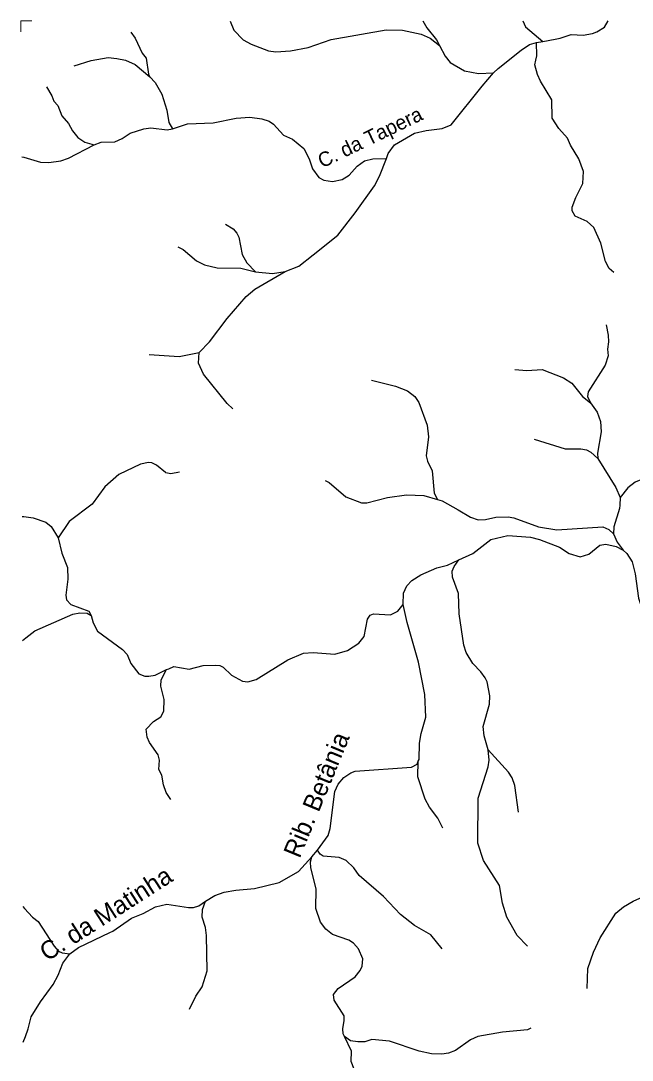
# Model space of a CAD drawing. Extents: x 473.9 to 500, y 7733.1 to 7760.8.
# Drawn here: x 473.88 to 477.26, y 7755.08 to 7760.81 of the extents above; entities that cross this region are included whole.
import ezdxf
from ezdxf.enums import TextEntityAlignment as Align

# ---------------------------------------------------------------- set-up
doc = ezdxf.new("R2010")
doc.units = 0
doc.header["$LTSCALE"] = 0.032
doc.layers.add('61', color=7, linetype='Continuous')
doc.layers.add('63', color=7, linetype='Continuous', lineweight=13)
doc.layers.add('7', color=7, linetype='Continuous', lineweight=25)

msp = doc.modelspace()

# ---------------------------------------------------------------- linework, layer by layer
at = {"layer": '63'}
msp.add_lwpolyline([(473.9466, 7760.8068), (473.885, 7760.8068), (473.885, 7760.7461)], dxfattribs=at)
at = {"layer": '7'}
for p, q in [((476.7287, 7760.6875), (476.7637, 7760.6941)), ((475.4907, 7756.1995), (475.5218, 7756.2363))]:
    msp.add_line(p, q, dxfattribs=at)
for points in [[(475.0392, 7760.8062), (475.0595, 7760.7562), (475.1122, 7760.7021), (475.1563, 7760.6781), (475.2516, 7760.6415), (475.2913, 7760.6366), (475.3731, 7760.6414), (475.4697, 7760.6609), (475.5973, 7760.7039), (475.8994, 7760.7575), (475.9898, 7760.7551), (476.0938, 7760.7344), (476.1422, 7760.7126), (476.1946, 7760.6706)], [(476.1017, 7760.807), (476.1246, 7760.7682), (476.1782, 7760.7022), (476.1946, 7760.6706)], [(476.6534, 7760.8074), (476.6684, 7760.7741), (476.6921, 7760.7542), (476.7637, 7760.6941)], [(476.7637, 7760.6941), (476.8311, 7760.7065), (476.8402, 7760.7081), (476.8603, 7760.7118), (476.9208, 7760.7318), (476.9864, 7760.728), (477.0377, 7760.7377), (477.0621, 7760.7461), (477.1033, 7760.772), (477.1242, 7760.8077)], [(474.4913, 7760.7452), (474.5162, 7760.7126), (474.555, 7760.6301), (474.5768, 7760.601), (474.5887, 7760.5127), (474.597, 7760.4988)], [(476.1946, 7760.6706), (476.2261, 7760.612), (476.2526, 7760.5783), (476.3318, 7760.5327), (476.4093, 7760.5179), (476.4912, 7760.5208)], [(476.4912, 7760.5208), (476.517, 7760.5446), (476.6444, 7760.6463), (476.6909, 7760.6771), (476.7287, 7760.6875)], [(477.156, 7759.4196), (477.1304, 7759.4426), (477.1088, 7759.4811), (477.0835, 7759.5818), (477.0456, 7759.6682), (477.0091, 7759.702), (476.9419, 7759.7306), (476.9264, 7759.76), (476.9265, 7759.7809), (476.9461, 7759.8341), (476.9837, 7759.9105), (476.9888, 7759.9765), (476.9626, 7760.0461), (476.9161, 7760.1215), (476.8995, 7760.1612), (476.8523, 7760.2142), (476.8158, 7760.2718), (476.8138, 7760.3726), (476.7509, 7760.4757), (476.7336, 7760.5118), (476.7197, 7760.5653), (476.7252, 7760.5901), (476.7307, 7760.6149), (476.7287, 7760.6875)], [(474.1795, 7760.5595), (474.2732, 7760.5886), (474.3676, 7760.6045), (474.4145, 7760.6005), (474.4629, 7760.5901), (474.5167, 7760.5668), (474.597, 7760.4988)], [(474.597, 7760.4988), (474.6262, 7760.4679), (474.6636, 7760.4035), (474.6909, 7760.3142), (474.7023, 7760.2465), (474.7217, 7760.2124)], [(475.9019, 7760.0492), (475.9107, 7760.0755), (475.9468, 7760.1235), (476.0566, 7760.1877), (476.121, 7760.2035), (476.2085, 7760.2137), (476.2591, 7760.2343), (476.4295, 7760.4481), (476.4912, 7760.5208)], [(474.026, 7760.4429), (474.0567, 7760.3935), (474.0669, 7760.3653), (474.0887, 7760.3405), (474.1118, 7760.2833), (474.1487, 7760.2423), (474.1707, 7760.2004), (474.2003, 7760.1646), (474.239, 7760.1393), (474.2891, 7760.1238)], [(474.7217, 7760.2124), (474.8036, 7760.2397), (474.9464, 7760.2459), (475.0719, 7760.2708), (475.1486, 7760.2774), (475.214, 7760.2677), (475.2554, 7760.254), (475.2782, 7760.2386), (475.3343, 7760.1778), (475.384, 7760.1545), (475.4452, 7760.1044), (475.475, 7760.0467), (475.4938, 7759.9913), (475.5282, 7759.9446), (475.556, 7759.9299), (475.6048, 7759.9213), (475.6572, 7759.9333), (475.6962, 7759.9572), (475.7403, 7760.0061), (475.7812, 7760.0366), (475.8267, 7760.0473), (475.9019, 7760.0492)], [(474.2891, 7760.1238), (474.3285, 7760.1386), (474.4043, 7760.1415), (474.4432, 7760.1586), (474.4884, 7760.1888), (474.5627, 7760.2131), (474.6024, 7760.2179), (474.6931, 7760.2076), (474.7217, 7760.2124)], [(473.8901, 7760.0586), (473.9012, 7760.0554), (473.9938, 7760.0287), (474.0393, 7760.0265), (474.105, 7760.0358), (474.1476, 7760.0498), (474.2891, 7760.1238)], [(475.3438, 7759.4258), (475.4181, 7759.4555), (475.4971, 7759.518), (475.6336, 7759.626), (475.7295, 7759.7484), (475.8347, 7759.8982), (475.8635, 7759.9509), (475.9019, 7760.0492)], [(475.0145, 7759.6859), (475.0569, 7759.6612), (475.0771, 7759.6365), (475.0867, 7759.6149), (475.1058, 7759.5199), (475.1323, 7759.4745), (475.1794, 7759.4242)], [(474.7503, 7759.5614), (474.7807, 7759.547), (474.8543, 7759.4856), (474.8976, 7759.4629), (474.9674, 7759.4467), (475.098, 7759.4451), (475.1794, 7759.4242)], [(474.8679, 7758.9796), (474.9264, 7759.0383), (475.0227, 7759.1674), (475.1274, 7759.289), (475.1758, 7759.3279), (475.3438, 7759.4258)], [(475.1794, 7759.4242), (475.2722, 7759.4155), (475.3438, 7759.4258)], [(477.1127, 7759.1312), (477.1245, 7759.0756), (477.1268, 7759.0384), (477.1196, 7758.997), (477.1235, 7758.9607), (477.1079, 7758.9101), (477.013, 7758.7623), (477.0098, 7758.7367), (477.0274, 7758.7028)], [(474.5921, 7758.9688), (474.7593, 7758.9584), (474.8679, 7758.9796)], [(475.0546, 7758.6684), (475.0225, 7758.6978), (474.892, 7758.8593), (474.8659, 7758.92), (474.8679, 7758.9796)], [(476.6101, 7758.8865), (476.6748, 7758.8806), (476.7606, 7758.8855), (476.8776, 7758.8408), (476.9233, 7758.81), (476.9825, 7758.7362), (477.0274, 7758.7028)], [(475.8194, 7758.8279), (475.9508, 7758.7942), (476.0169, 7758.7681), (476.0589, 7758.7369), (476.0792, 7758.704), (476.1261, 7758.5788), (476.1326, 7758.514), (476.1214, 7758.4105), (476.1274, 7758.3803), (476.1528, 7758.3268), (476.1643, 7758.2039), (476.1823, 7758.1699)], [(477.0274, 7758.7028), (477.0641, 7758.6508), (477.0811, 7758.6), (477.0851, 7758.5432), (477.0659, 7758.4243), (477.0675, 7758.3957)], [(476.7153, 7758.5026), (476.8872, 7758.4477), (476.9734, 7758.4492), (477.0049, 7758.4428), (477.0287, 7758.431), (477.0675, 7758.3957)], [(474.7611, 7758.3202), (474.7121, 7758.3114), (474.6844, 7758.317), (474.6828, 7758.3173), (474.6333, 7758.3578), (474.6069, 7758.3719), (474.5885, 7758.3739), (474.5448, 7758.3633), (474.4262, 7758.3072), (474.3485, 7758.2396), (474.2792, 7758.1433), (474.1512, 7758.0489), (474.092, 7757.9588)], [(477.0675, 7758.3957), (477.167, 7758.2356), (477.1911, 7758.1801)], [(475.5641, 7758.2746), (475.5857, 7758.2634), (475.6782, 7758.1837), (475.7631, 7758.1502), (475.7931, 7758.1508), (475.9072, 7758.1808), (476.0112, 7758.1943), (476.1078, 7758.1911), (476.1823, 7758.1699)], [(477.7102, 7758.2126), (477.6638, 7758.2344), (477.5594, 7758.2673), (477.4317, 7758.2905), (477.383, 7758.2905), (477.2949, 7758.2743), (477.2728, 7758.264), (477.2325, 7758.2342), (477.1911, 7758.1801)], [(476.1823, 7758.1699), (476.2095, 7758.1621), (476.2965, 7758.1119), (476.3653, 7758.0723), (476.4081, 7758.0572), (476.4474, 7758.0585), (476.5053, 7758.0717), (476.5723, 7758.074), (476.6031, 7758.069), (476.74, 7758.0188), (476.8402, 7758.0027), (477.0947, 7758.0195), (477.1284, 7758.0042), (477.1538, 7757.9796)], [(477.1911, 7758.1801), (477.1877, 7758.1383), (477.1862, 7758.1193), (477.1557, 7758.0183), (477.1538, 7757.9796)], [(473.8932, 7758.0761), (473.9025, 7758.075), (473.9538, 7758.0692), (474.0223, 7758.0443), (474.0529, 7758.0201), (474.092, 7757.9588)], [(474.092, 7757.9588), (474.112, 7757.8738), (474.1425, 7757.795), (474.1441, 7757.7308), (474.133, 7757.6415), (474.1377, 7757.6165), (474.1617, 7757.5903), (474.261, 7757.5538), (474.2734, 7757.5308)], [(476.3014, 7757.8363), (476.377, 7757.8713), (476.4772, 7757.9484), (476.5716, 7757.9706), (476.6967, 7757.9626), (476.7458, 7757.9495), (476.8553, 7757.9058), (476.9082, 7757.8722), (476.969, 7757.8536), (477.0183, 7757.8678), (477.079, 7757.9185), (477.111, 7757.9224), (477.1686, 7757.9096), (477.2076, 7757.8896)], [(477.1538, 7757.9796), (477.1743, 7757.934), (477.2076, 7757.8896)], [(477.2076, 7757.8896), (477.2271, 7757.8711), (477.2567, 7757.8251), (477.2734, 7757.7588), (477.292, 7757.6263), (477.3268, 7757.5202), (477.3543, 7757.481), (477.4148, 7757.4218), (477.4448, 7757.4073), (477.4983, 7757.3954), (477.816, 7757.3677), (477.9231, 7757.3226)], [(475.9943, 7757.5902), (475.9955, 7757.6523), (476.0134, 7757.6944), (476.0423, 7757.7237), (476.0912, 7757.7543), (476.1795, 7757.7922), (476.2384, 7757.8071), (476.3014, 7757.8363)], [(476.4633, 7756.7906), (476.4397, 7756.8662), (476.4357, 7756.9185), (476.4694, 7757.0417), (476.4725, 7757.0866), (476.4565, 7757.1648), (476.4464, 7757.1866), (476.4226, 7757.2204), (476.3771, 7757.2646), (476.3409, 7757.327), (476.3291, 7757.3665), (476.3026, 7757.5394), (476.2994, 7757.652), (476.266, 7757.741), (476.2641, 7757.7737), (476.2751, 7757.801), (476.3014, 7757.8363)], [(474.6888, 7757.232), (474.7012, 7757.237), (474.7291, 7757.2481), (474.8127, 7757.2337), (474.8914, 7757.2538), (474.9594, 7757.257), (474.9834, 7757.2539), (475.0014, 7757.2445), (475.0479, 7757.2019), (475.1073, 7757.1675), (475.1371, 7757.1649), (475.1823, 7757.1771), (475.357, 7757.2854), (475.4446, 7757.3219), (475.4982, 7757.3268), (475.617, 7757.3168), (475.6176, 7757.3167), (475.6858, 7757.3374), (475.7496, 7757.3775), (475.7792, 7757.414), (475.7968, 7757.5104), (475.8118, 7757.5319), (475.8301, 7757.5385), (475.9238, 7757.5344), (475.9648, 7757.5537), (475.9943, 7757.5902)], [(476.077, 7756.7266), (476.0817, 7756.737), (476.0829, 7756.826), (476.0923, 7756.8803), (476.1189, 7756.9704), (476.1133, 7757.0949), (476.0781, 7757.2735), (476.0155, 7757.4919), (475.9943, 7757.5902)], [(473.8942, 7757.3926), (473.9126, 7757.4071), (473.9616, 7757.4456), (474.1724, 7757.5366), (474.2112, 7757.5456), (474.2503, 7757.5423), (474.2734, 7757.5308)], [(474.2734, 7757.5308), (474.2839, 7757.4894), (474.3077, 7757.4446), (474.3362, 7757.4237), (474.4459, 7757.3434), (474.4713, 7757.3149), (474.4927, 7757.2664), (474.5357, 7757.2088), (474.5688, 7757.1953), (474.5915, 7757.1952), (474.6263, 7757.2012), (474.6888, 7757.232)], [(474.7122, 7756.5153), (474.6866, 7756.5546), (474.6726, 7756.5962), (474.6637, 7756.6509), (474.647, 7756.6814), (474.6502, 7756.7323), (474.6435, 7756.7614), (474.5949, 7756.8309), (474.5823, 7756.8591), (474.5773, 7756.9027), (474.6178, 7756.9462), (474.657, 7756.972), (474.6742, 7757.0021), (474.6765, 7757.0673), (474.6574, 7757.1403), (474.659, 7757.176), (474.6888, 7757.232)], [(476.6796, 7755.7078), (476.6215, 7755.7664), (476.565, 7755.867), (476.5416, 7755.9442), (476.5244, 7756.0414), (476.4363, 7756.1803), (476.4053, 7756.2761), (476.4068, 7756.523), (476.463, 7756.6952), (476.4677, 7756.7331), (476.4633, 7756.7906)], [(476.6303, 7756.4464), (476.6096, 7756.5923), (476.5951, 7756.6359), (476.5745, 7756.6675), (476.4633, 7756.7906)], [(475.5218, 7756.2363), (475.5801, 7756.3182), (475.5904, 7756.3559), (475.6167, 7756.5606), (475.6356, 7756.6006), (475.6657, 7756.637), (475.7042, 7756.6627), (475.7297, 7756.6718), (476.0392, 7756.6941), (476.07, 7756.7111), (476.077, 7756.7266)], [(476.2122, 7756.3578), (476.1846, 7756.413), (476.1386, 7756.4732), (476.1145, 7756.518), (476.0749, 7756.6416), (476.077, 7756.7266)], [(474.9037, 7755.9565), (474.9552, 7755.9868), (475.0069, 7756.0054), (475.0703, 7756.0166), (475.1743, 7756.0247), (475.3106, 7756.0583), (475.4172, 7756.1198), (475.4907, 7756.1995)], [(475.6703, 7755.2102), (475.6625, 7755.2249), (475.6611, 7755.2514), (475.6691, 7755.2979), (475.6675, 7755.3244), (475.6136, 7755.4093), (475.6091, 7755.4414), (475.6352, 7755.4751), (475.7283, 7755.5393), (475.7559, 7755.5727), (475.7676, 7755.5978), (475.7716, 7755.6373), (475.7473, 7755.6921), (475.7206, 7755.724), (475.6949, 7755.7411), (475.604, 7755.7723), (475.5681, 7755.8009), (475.5375, 7755.8405), (475.5114, 7755.916), (475.5145, 7756.0243), (475.4849, 7756.1394), (475.4835, 7756.1723), (475.4907, 7756.1995)], [(476.2092, 7755.6924), (476.1468, 7755.7707), (476.057, 7755.822), (475.9793, 7755.8813), (475.8854, 7755.9816), (475.7514, 7756.098), (475.721, 7756.1388), (475.6801, 7756.18), (475.6406, 7756.1962), (475.5531, 7756.2037), (475.536, 7756.2148), (475.5218, 7756.2363)], [(477.0082, 7755.475), (477.0127, 7755.5842), (477.0432, 7755.6744), (477.08, 7755.753), (477.1666, 7755.8889), (477.2079, 7755.9251), (477.2624, 7755.9565), (477.4049, 7756.0201), (477.4835, 7756.0385)], [(474.1559, 7755.6657), (474.203, 7755.7004), (474.3755, 7755.7824), (474.393, 7755.7907), (474.496, 7755.8614), (474.5602, 7755.8879), (474.6271, 7755.9245), (474.6909, 7755.9389), (474.809, 7755.9205), (474.8372, 7755.9213), (474.8667, 7755.9298), (474.9037, 7755.9565)], [(474.8159, 7755.3601), (474.8509, 7755.4316), (474.8849, 7755.4832), (474.9122, 7755.5725), (474.909, 7755.7669), (474.9029, 7755.8103), (474.8851, 7755.8676), (474.888, 7755.9098), (474.9037, 7755.9565)], [(473.8964, 7755.926), (473.9062, 7755.9152), (473.95, 7755.867), (473.9803, 7755.8434), (474.0684, 7755.7077), (474.0924, 7755.6804), (474.1128, 7755.671), (474.1559, 7755.6657)], [(473.8976, 7755.1783), (473.9119, 7755.2102), (473.9254, 7755.2529), (473.9415, 7755.3183), (473.9933, 7755.4005), (474.0634, 7755.4958), (474.0919, 7755.5482), (474.1166, 7755.6141), (474.1559, 7755.6657)], [(476.6984, 7755.2559), (476.6788, 7755.247), (476.5412, 7755.2335), (476.4047, 7755.21), (476.3657, 7755.1919), (476.2819, 7755.1335), (476.2436, 7755.1183), (476.207, 7755.1123), (476.1506, 7755.1146), (476.0825, 7755.1283), (475.919, 7755.1845), (475.82, 7755.1932), (475.7818, 7755.1813), (475.7429, 7755.1796), (475.704, 7755.1863), (475.6703, 7755.2102)], [(475.7461, 7754.939), (475.7396, 7754.9869), (475.7069, 7755.0721), (475.7082, 7755.1289), (475.6703, 7755.2102)]]:
    msp.add_lwpolyline(points, dxfattribs=at)

# ---------------------------------------------------------------- texts
at = {"layer": '61'}
for s, height, rotation, p in [('C. da Tapera', 0.08, 25.769, (475.8283, 7760.1297)), ('Rib. Betânia', 0.1, 67.574, (475.5616, 7756.5238)), ('C. da Matinha', 0.1, 32.607, (474.3807, 7755.8455))]:
    msp.add_text(s, height=height, rotation=rotation, dxfattribs=at).set_placement(p, align=Align.CENTER)

doc.saveas('drawing.dxf')
